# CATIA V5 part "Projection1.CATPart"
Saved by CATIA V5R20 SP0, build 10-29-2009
Part number: Part1
Bounding box of the stored display mesh (mm): x 0 to 188, y 0 to 140, z -145.869 to 107.525
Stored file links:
  J:\카티아자료\수업자료\툴바예제\6 GSD\Wireframe\Projection1.CATPart
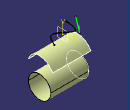
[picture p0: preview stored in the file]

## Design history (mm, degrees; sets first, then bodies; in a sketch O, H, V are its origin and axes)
Set1
  Sketch1 on yz-plane, origin (0, 0, 0), H (0, 1, 0), V (0, 0, 1)
    spline S1 through (20, 0) (40, 30) (80, 40) (110, 30) (140, 0)
  Extrude1: Element1 Sketch1, Lim1 188, Lim2 0, Direction yz-plane
  Plane1: type Offset, RefPlane xy-plane, Offset 85
  Sketch2 on Plane1, origin (0, 0, 85), H (1, 0, 0), V (0, 1, 0)
    spline S1 through (20, 40) (40, 100) (110, 60) (150, 110)
  Sketch3 on yz-plane, origin (0, 0, 0), H (0, 1, 0), V (0, 0, 1)
    line L1 (64.1582, 107.5253) -> (84.1582, 47.5253)
  Extract1: ExtractElem element of Sketch2
  Extract2: ExtractElem element of Sketch3
  Sketch4 on yz-plane, origin (0, 0, 0), H (0, 1, 0), V (0, 0, 1)
    circle A1 centre (74.5158, -91.3323) radius 54.546
  Extrude2: Element1 Sketch4, Lim1 188, Lim2 0, Direction yz-plane
Body1 "PartBody" (main body)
